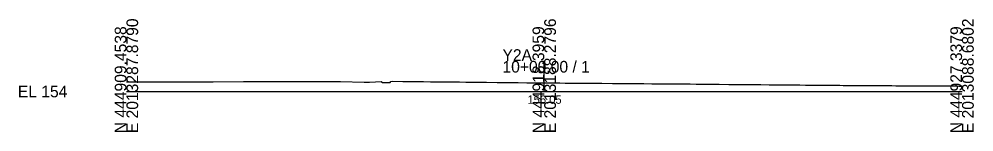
# Model space of a CAD drawing. Extents: x -26 to 203, y -10 to 5517.
# Drawn here: x -25.7 to 202.8, y -9.7 to 17.3 of the extents above; entities that cross this region are included whole.
import ezdxf

# ---------------------------------------------------------------- set-up
doc = ezdxf.new("R2010")
doc.units = 0
for name, color, linetype in [('Default', 7, 'Continuous'), ('Exist Cross Section Cell', 7, 'Continuous'), ('Exist XS Center Line Elevation Label', 7, 'Continuous'), ('Exist XS Ground Line', 7, 'Continuous')]:
    doc.layers.add(name, color=color, linetype=linetype)

msp = doc.modelspace()

# ---------------------------------------------------------------- linework, layer by layer
at = {"layer": 'Exist Cross Section Cell'}
for p, q in [((100, 0), (100, 7.32)), ((0, 0), (100, 0)), ((100, 0), (200, 0))]:
    msp.add_line(p, q, dxfattribs=at)
at = {"layer": 'Exist XS Ground Line'}
msp.add_lwpolyline([(0, 2.29), (2.82, 2.33), (8.04, 2.34), (13.97, 2.34), (20.75, 2.34), (28, 2.37), (34.65, 2.37), (42.09, 2.39), (44.08, 2.38), (51.25, 2.42), (56.93, 2.2), (57.71, 2.2), (58.2, 2.22), (59.6, 2.28), (60.95, 2.36), (61.29, 2.15), (61.97, 2.15), (63.14, 2.17), (63.26, 2.39), (63.68, 2.44), (66.14, 2.41), (68.19, 2.39), (68.64, 2.38), (69.18, 2.38), (71.14, 2.36), (72.79, 2.34), (73.66, 2.32), (74.7, 2.31), (76.18, 2.3), (77.48, 2.29), (78.69, 2.28), (79.7, 2.27), (81.2, 2.25), (82.98, 2.22), (83.69, 2.22), (85.75, 2.19), (86.21, 2.19), (88.71, 2.16), (91.24, 2.14), (93.75, 2.11), (95.82, 2.09), (96.26, 2.09), (96.78, 2.09), (98.76, 2.07), (99.53, 2.06), (100, 2.05), (101.26, 2.04), (102.7, 2.03), (103.77, 2.03), (105.02, 2.02), (106.29, 2.01), (107.34, 2), (108.8, 1.99), (110.55, 1.97), (111.31, 1.97), (113.33, 1.95), (113.82, 1.95), (116.33, 1.93), (118.83, 1.92), (121.61, 1.9), (123.86, 1.88), (125.75, 1.86), (126.37, 1.86), (127.11, 1.85), (128.88, 1.84), (129.88, 1.83), (131.39, 1.82), (132.63, 1.81), (133.9, 1.79), (134.95, 1.79), (136.4, 1.77), (137.26, 1.77), (138.92, 1.75), (139.57, 1.75), (141.43, 1.73), (141.87, 1.73), (144.18, 1.7), (146.49, 1.68), (146.86, 1.68), (149.12, 1.66), (151.35, 1.64), (151.82, 1.63), (153.8, 1.61), (154.52, 1.6), (156.24, 1.59), (157.2, 1.58), (158.69, 1.57), (159.87, 1.56), (161.15, 1.55), (162.54, 1.53), (163.61, 1.52), (164.02, 1.52), (165.21, 1.51), (166.06, 1.51), (166.53, 1.5), (167.62, 1.49), (168.29, 1.49), (169.04, 1.48), (170.23, 1.47), (170.74, 1.47), (171.55, 1.46), (172.83, 1.45), (173.19, 1.45), (174.06, 1.45), (175.65, 1.43), (176.17, 1.43), (177.48, 1.42), (178.29, 1.42), (179.93, 1.4), (180.6, 1.4), (183.19, 1.39), (184.19, 1.38), (184.56, 1.38), (186.69, 1.37), (187.29, 1.37), (189.19, 1.35), (190.05, 1.35), (191.69, 1.34), (192.84, 1.33), (194.19, 1.32), (195.68, 1.32), (196.68, 1.32), (198.58, 1.31), (199.23, 1.3), (200, 1.3)], dxfattribs=at)

# ---------------------------------------------------------------- texts
at = {"layer": 'Default'}
msp.add_text('-', height=0.0001, dxfattribs=at).set_placement((0, 0))
at = {"layer": 'Exist Cross Section Cell'}
for s, p in [('E 2013287.8790', (2.8, -10)), ('E 2013188.2796', (102.8, -10)), ('E 2013088.6802', (202.8, -10)), ('N 444909.4538', (0, -10)), ('N 444918.3959', (100, -10)), ('N 444927.3379', (200, -10))]:
    msp.add_text(s, height=2.8, rotation=90, dxfattribs=at).set_placement(p)
for s, p in [('Y2A', (90, 7.32)), ('10+00.00 / 1', (90, 4.52)), ('EL 154', (-26, -1.4))]:
    msp.add_text(s, height=2.8, dxfattribs=at).set_placement(p)
at = {"layer": 'Exist XS Center Line Elevation Label'}
msp.add_text('156.05', height=2, dxfattribs=at).set_placement((95.98, -2.95))

doc.saveas('drawing.dxf')
